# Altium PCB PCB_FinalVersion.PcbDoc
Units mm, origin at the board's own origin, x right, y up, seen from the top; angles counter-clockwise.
Board outline 269.9 x 119.9 mm, 2 copper layers (Top Layer, Bottom Layer); 54 components, 78 nets, 205 pads, 10 vias.
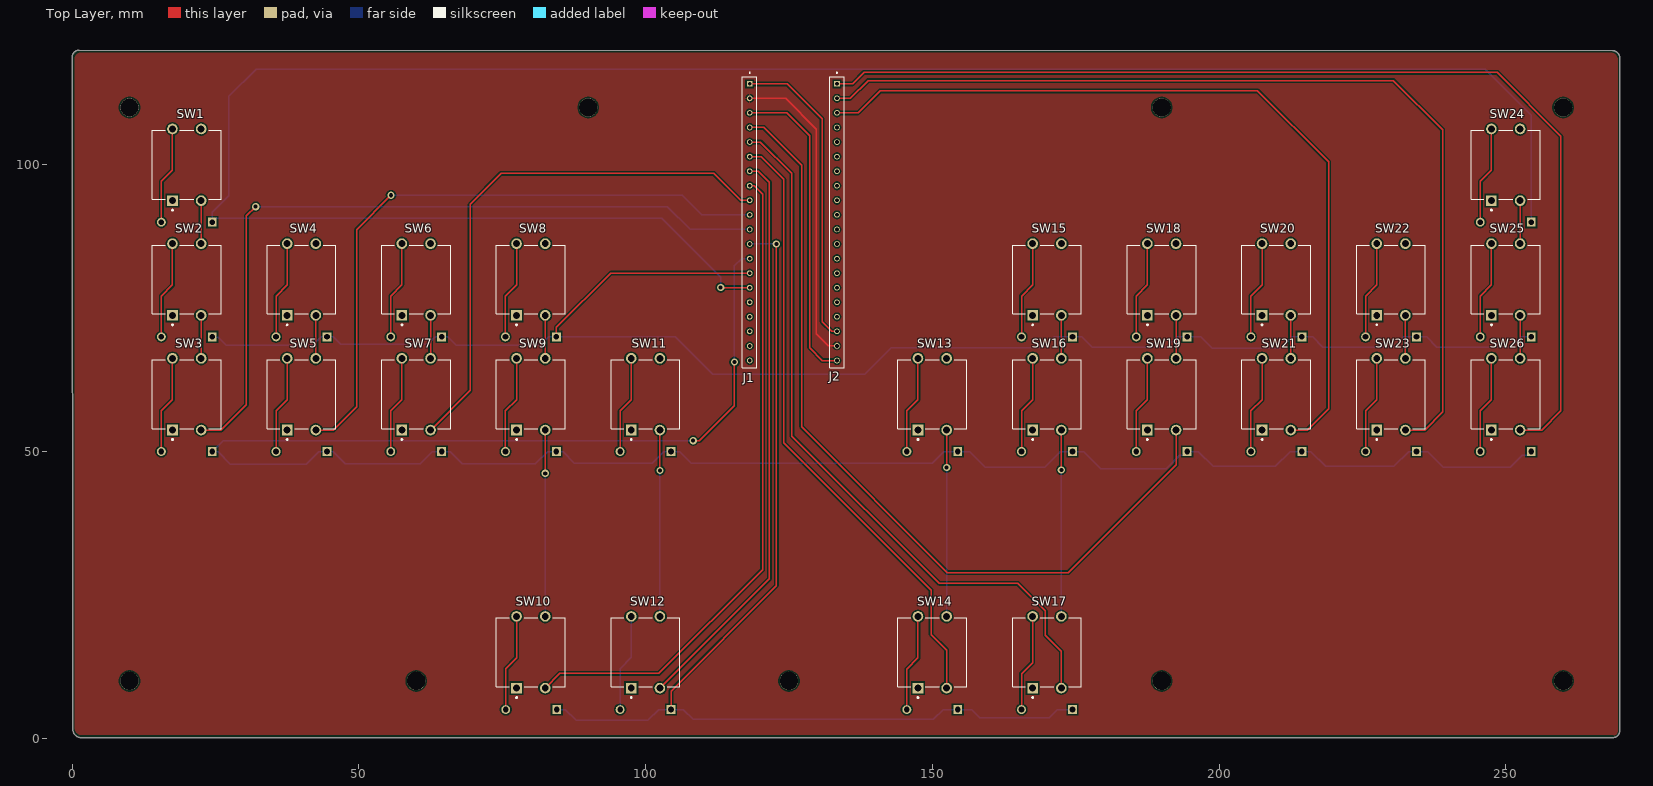
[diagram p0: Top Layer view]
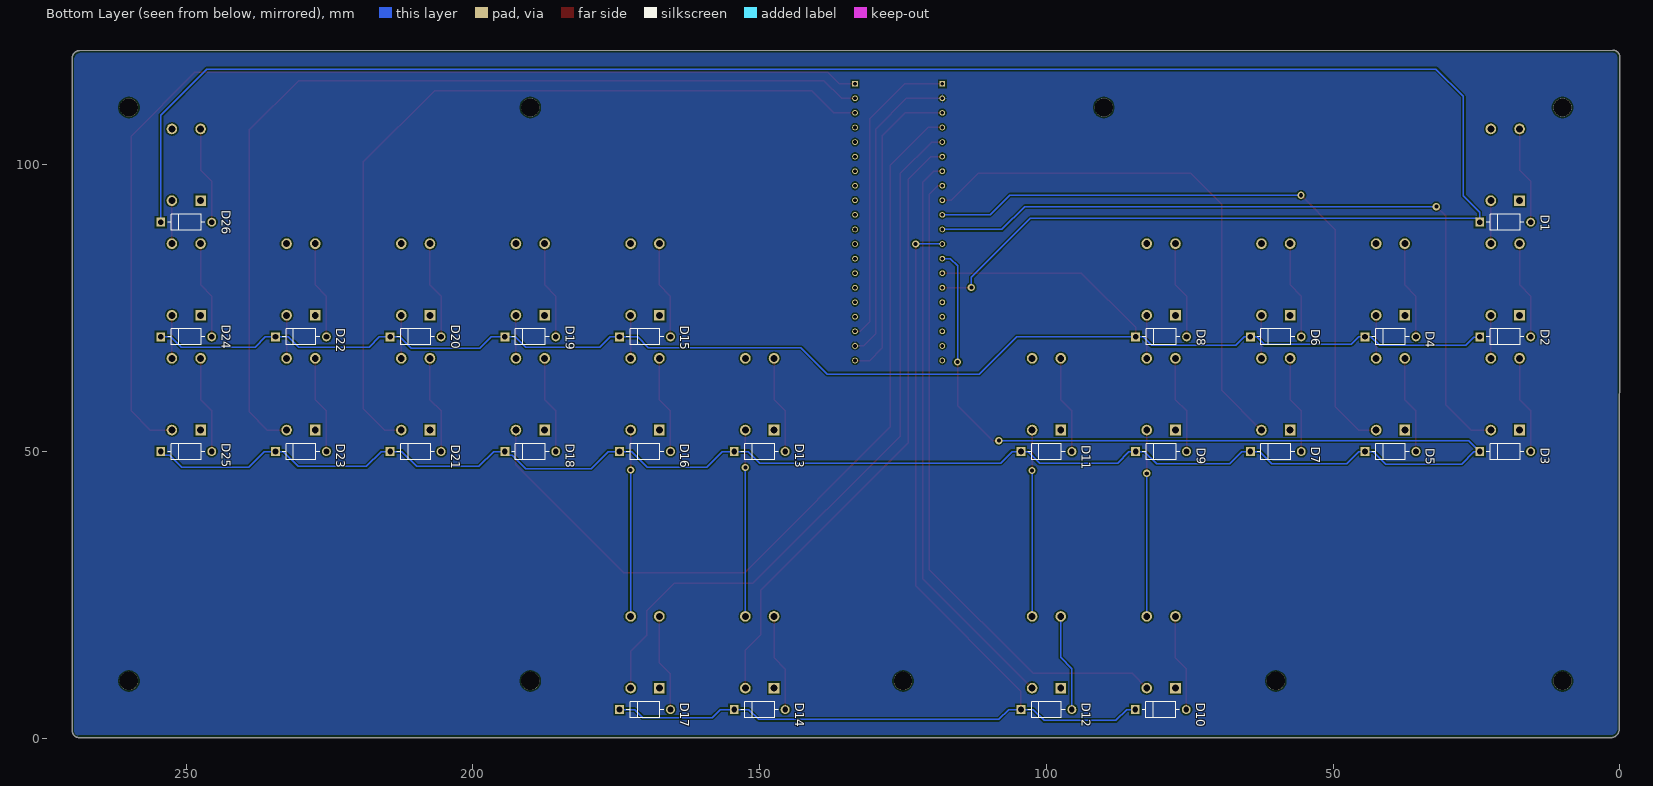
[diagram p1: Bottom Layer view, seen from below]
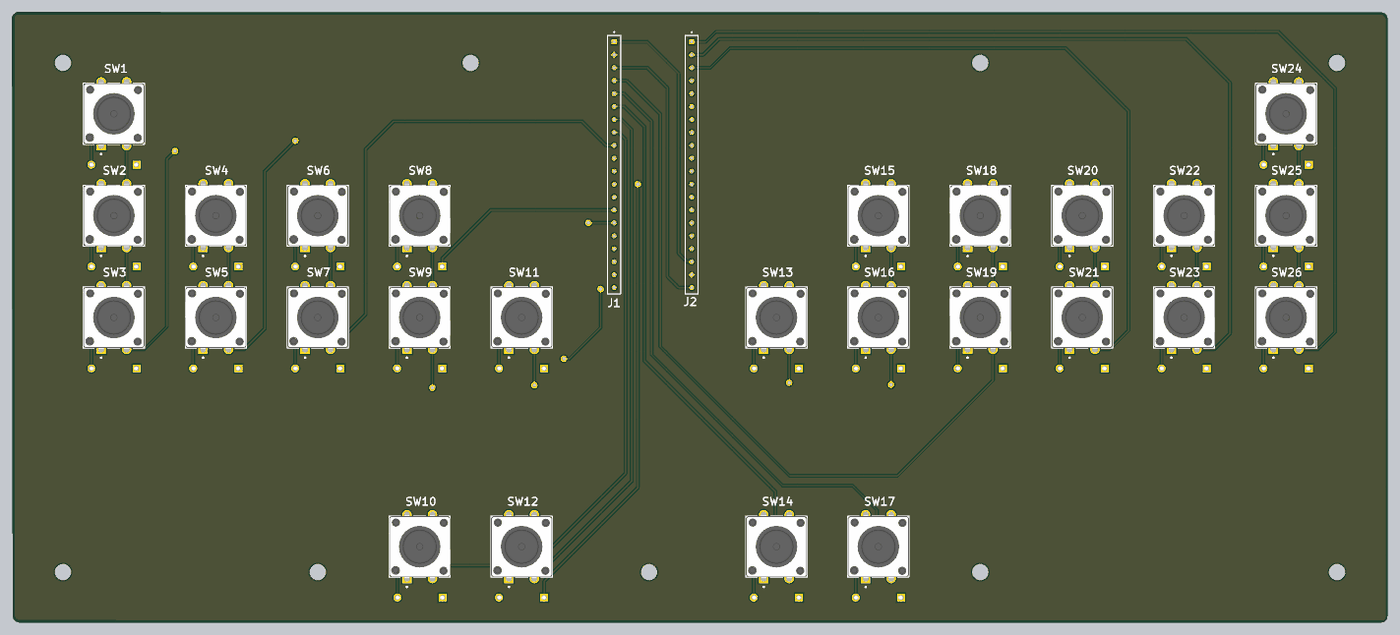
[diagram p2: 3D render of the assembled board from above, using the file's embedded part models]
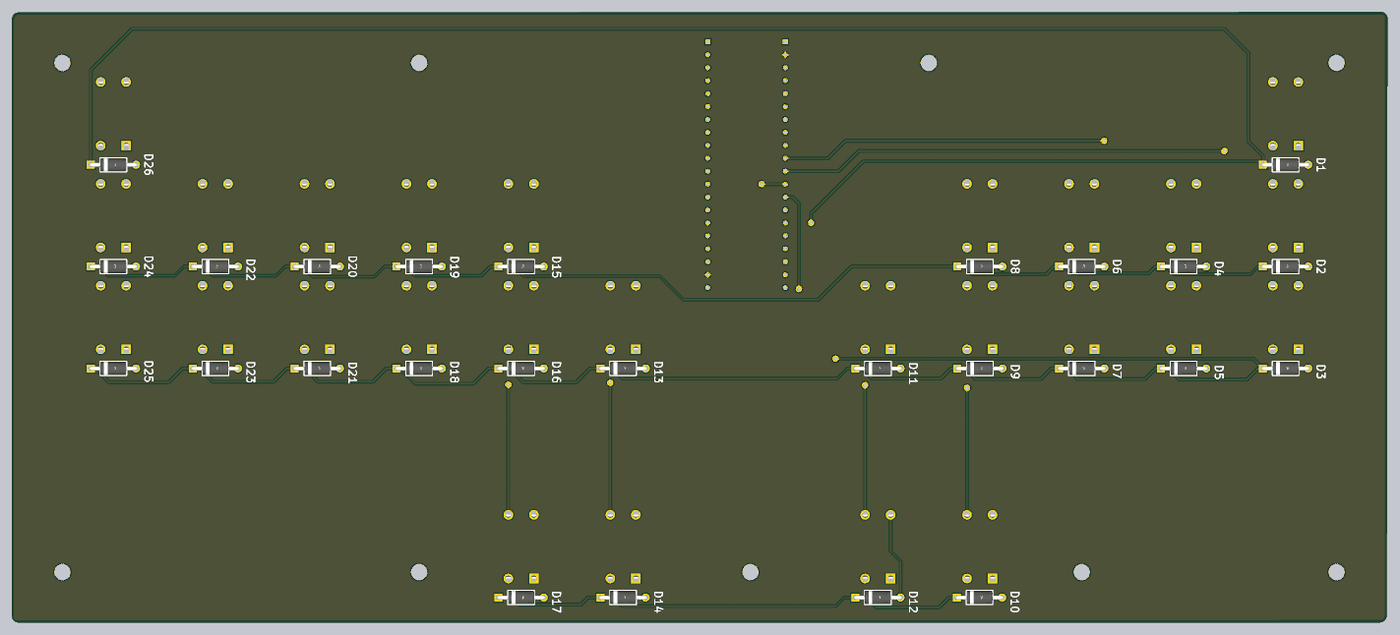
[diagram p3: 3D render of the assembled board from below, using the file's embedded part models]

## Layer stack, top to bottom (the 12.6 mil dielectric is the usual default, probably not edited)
Top Solder: solder mask 0.0102, Solder Resist, Dk 3.5
Top Layer: signal copper 0.0356
Dielectric 1: dielectric 0.32, FR-4, Dk 4.8
Bottom Layer: signal copper 0.0356
Bottom Solder: solder mask 0.0102, Solder Resist, Dk 3.5

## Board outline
0.129,1.541 ccw(c1.57,1.541) 1.57,0.1 5,0.1 268.63,0.1 ccw(c268.63,1.37) 269.9,1.37 269.9,118.63 ccw(c268.63,118.63) 268.63,119.9 1.217,120 ccw(c1.217,118.783) 0,118.783

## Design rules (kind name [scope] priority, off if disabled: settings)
Clearance [All] p1: gap=0.254 ignorepadtopadclearanceinfootprint=FALSE except(0: Arc-Hole Track-Hole SMDPad-Hole THPad-Hole Via-Hole Fill-Hole Poly-Hole Region-Hole Text-Hole)
PolygonConnect [All] p1: connectstyle=Relief reliefconductorwidth=0.254 reliefentries=4 polygonreliefangle="90 Angle" airgapwidth=0.254
RoutingVias [All] p1: holewidth=0.711 width=1.27 viastyle="Through Hole" minholewidth=0.711 minwidth=1.27 maxholewidth=0.711 maxwidth=1.27
SolderMaskExpansion [All] p1: expansion=0.102 istentingtop=FALSE
Width [All] p1: maxlimit=0.5 minlimit=0.254 preferedwidth=0.3
30 further rules are at their usual default settings.

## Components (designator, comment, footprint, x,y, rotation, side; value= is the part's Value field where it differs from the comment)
D1 "1N4007" FP-1N4007-MFG 20,90 r180 bottom value=15pF
D2 "1N4007" FP-1N4007-MFG 20,70 r180 bottom value=15pF
D3 "1N4007" FP-1N4007-MFG 20,50 r180 bottom value=15pF
D4 "1N4007" FP-1N4007-MFG 40,70 r180 bottom value=15pF
D5 "1N4007" FP-1N4007-MFG 40,50 r180 bottom value=15pF
D6 "1N4007" FP-1N4007-MFG 60,70 r180 bottom value=15pF
D7 "1N4007" FP-1N4007-MFG 60,50 r180 bottom value=15pF
D8 "1N4007" FP-1N4007-MFG 80,70 r180 bottom value=15pF
D9 "1N4007" FP-1N4007-MFG 80,50 r180 bottom value=15pF
D10 "1N4007" FP-1N4007-MFG 80.061,5 r180 bottom value=15pF
D11 "1N4007" FP-1N4007-MFG 100,50 r180 bottom value=15pF
D12 "1N4007" FP-1N4007-MFG 100,5 r180 bottom value=15pF
D13 "1N4007" FP-1N4007-MFG 150,50 r180 bottom value=15pF
D14 "1N4007" FP-1N4007-MFG 150,5 r180 bottom value=15pF
D15 "1N4007" FP-1N4007-MFG 170,70 r180 bottom value=15pF
D16 "1N4007" FP-1N4007-MFG 170,50 r180 bottom value=15pF
D17 "1N4007" FP-1N4007-MFG 170,5 r180 bottom value=15pF
D18 "1N4007" FP-1N4007-MFG 190,50 r180 bottom value=15pF
D19 "1N4007" FP-1N4007-MFG 190,70 r180 bottom value=15pF
D20 "1N4007" FP-1N4007-MFG 210,70 r180 bottom value=15pF
D21 "1N4007" FP-1N4007-MFG 210,50 r180 bottom value=15pF
D22 "1N4007" FP-1N4007-MFG 230,70 r180 bottom value=15pF
D23 "1N4007" FP-1N4007-MFG 230,50 r180 bottom value=15pF
D24 "1N4007" FP-1N4007-MFG 250,70 r180 bottom value=15pF
D25 "1N4007" FP-1N4007-MFG 250,50 r180 bottom value=15pF
D26 "1N4007" FP-1N4007-MFG 250,90 r180 bottom value=15pF
J1 "TS-120-T-AA" SAMTEC_TS-120-T-AA 118.156,90 r270 top
J2 "TS-120-T-AA" SAMTEC_TS-120-T-AA 133.376,90 r270 top
SW1 "MJTP1212A" FP-MJTP1212A-MFG 20,100 r90 top
SW2 "MJTP1212A" FP-MJTP1212A-MFG 20,80 r90 top
SW3 "MJTP1212A" FP-MJTP1212A-MFG 20,60 r90 top
SW4 "MJTP1212A" FP-MJTP1212A-MFG 40,80 r90 top
SW5 "MJTP1212A" FP-MJTP1212A-MFG 40,60 r90 top
SW6 "MJTP1212A" FP-MJTP1212A-MFG 60,80 r90 top
SW7 "MJTP1212A" FP-MJTP1212A-MFG 60,60 r90 top
SW8 "MJTP1212A" FP-MJTP1212A-MFG 80,80 r90 top
SW9 "MJTP1212A" FP-MJTP1212A-MFG 80,60 r90 top
SW10 "MJTP1212A" FP-MJTP1212A-MFG 80,15 r90 top
SW11 "MJTP1212A" FP-MJTP1212A-MFG 100,60 r90 top
SW12 "MJTP1212A" FP-MJTP1212A-MFG 100,15 r90 top
SW13 "MJTP1212A" FP-MJTP1212A-MFG 150,60 r90 top
SW14 "MJTP1212A" FP-MJTP1212A-MFG 150,15 r90 top
SW15 "MJTP1212A" FP-MJTP1212A-MFG 170,80 r90 top
SW16 "MJTP1212A" FP-MJTP1212A-MFG 170,60 r90 top
SW17 "MJTP1212A" FP-MJTP1212A-MFG 170,15 r90 top
SW18 "MJTP1212A" FP-MJTP1212A-MFG 190,80 r90 top
SW19 "MJTP1212A" FP-MJTP1212A-MFG 190,60 r90 top
SW20 "MJTP1212A" FP-MJTP1212A-MFG 210,80 r90 top
SW21 "MJTP1212A" FP-MJTP1212A-MFG 210,60 r90 top
SW22 "MJTP1212A" FP-MJTP1212A-MFG 230,80 r90 top
SW23 "MJTP1212A" FP-MJTP1212A-MFG 230,60 r90 top
SW24 "MJTP1212A" FP-MJTP1212A-MFG 250,100 r90 top
SW25 "MJTP1212A" FP-MJTP1212A-MFG 250,80 r90 top
SW26 "MJTP1212A" FP-MJTP1212A-MFG 250,60 r90 top

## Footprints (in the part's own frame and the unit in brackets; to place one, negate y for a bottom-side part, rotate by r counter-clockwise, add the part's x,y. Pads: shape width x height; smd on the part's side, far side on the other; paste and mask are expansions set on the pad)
FP-1N4007-MFG [mm]
  rect 1.55x1.55 hole 1 paste-2539.97 mask+0: 1(-4.44,0)
  round 1.55 hole 1 paste-2539.97 mask+0: 2(4.44,0)
  silkscreen extent -3.27,-1.4 3.27,1.4, body extent -4.83,-1.29 4.83,1.29, height 2.6
FP-MJTP1212A-MFG [mm]
  rect 1.85x1.85 hole 1.2 paste-2539.97 mask+0: 1(-6.25,2.5)
  round 1.85 hole 1.2 paste-2539.97 mask+0: 2(6.25,2.5) 3(-6.25,-2.5) 4(6.25,-2.5)
  silkscreen extent -8.02,-6 6,6, body extent -7.27,-6.1 7.27,6.1, height 0.25
SAMTEC_TS-120-T-AA [mm]
  rect 0.985x0.985 / inner round 0.985 / far side rect 0.985x0.985 hole 0.635: 01(-24.13,0)
  round 0.985 hole 0.635: 02(-21.59,0) 03(-19.05,0) 04(-16.51,0) 05(-13.97,0) 06(-11.43,0) 07(-8.89,0) 08(-6.35,0) 09(-3.81,0) 10(-1.27,0) 11(1.27,0) 12(3.81,0) 13(6.35,0) 14(8.89,0) 15(11.43,0) 16(13.97,0) 17(16.51,0) 18(19.05,0) 19(21.59,0) 20(24.13,0)
  silkscreen extent -26.15,-1.27 25.4,1.27

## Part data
D1 D2 D3 D4 D5 D6 D7 D8 D9 D10 D11 D12 D13 D14 D15 D16 D17 D18 D19 D20 D21 D22 D23 D24 D25 D26: library part CMP-123542-000001-1, "Rectifier diode 1000 V 1 A DO-41, ,", Capacitance=15pF, Forward Current=1A, Manufacturer=Diotec, Max Junction Temp=+175°C, Max Repetitive Reverse Voltage=1000V, Max Surge Forward Current=27A, Peak Reverse Current=5uA, Temperature="-50°C to +175°C", Temperature Range Low=-50°C
J1 J2: "Headers & Wire Housings .100 Single Row Screw Machine Terminal Strip", Package=None
SW1 SW2 SW3 SW4 SW5 SW6 SW7 SW8 SW9 SW10 SW11 SW12 SW13 SW14 SW15 SW16 SW17 SW18 SW19 SW20 SW21 SW22 SW23 SW24 SW25 SW26: library part CMP-47024-000003-1, "SWITCH TACTILE SPST-NO 0.05A 12V", Contact Resistance=100mR, Current Rating=50mA, Max Operating Temperature=70°C, Max Voltage Rating (DC)=12V, Min Operating Temperature=-20°C, Operating Force=160gf, Package Quantity=100

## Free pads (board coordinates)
  round 3.2 hole 3.2: 4(10,10) 4(10,110) 4(60,10) 4(90,110) 4(125,10) 4(190,10) 4(190,110) 4(260,10) 4(260,110)

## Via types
v1: diameter 1.27, hole 0.711, Top Layer to Bottom Layer, 10 vias

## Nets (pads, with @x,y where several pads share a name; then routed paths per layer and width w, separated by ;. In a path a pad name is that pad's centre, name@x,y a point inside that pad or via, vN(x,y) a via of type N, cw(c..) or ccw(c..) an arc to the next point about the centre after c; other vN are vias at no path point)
3.3V: J1.03 J2.20 | length 54.8
  Top Layer w0.254: J1.03 124.65,109.05 128.6,105.1 128.6,68.1 130.83,65.87 J2.20
5V: J1.01 J2.18 | length 53.8
  Top Layer w0.254: J1.01 124.67,114.13 130.8,108 130.8,72.6 132.45,70.95 J2.18
A8: J2.05
A9: J2.06
A10: J2.07
A11: J2.08
A12: J2.09
A15: J2.10
B3: J2.11
B4: J2.12
B5: J2.13
B6: J2.14
B7: J2.15
B8: J2.16
B9: J2.17
B15: J2.04
C13: J1.19
C14: J1.18
C15: J1.17
Column1: J1.11 SW3.3 | length 132.7
  Top Layer w0.254: SW3.3 25.95,53.75 30.4,58.2 30.4,91.1 v1(32,92.7)
  Bottom Layer w0.254: v1(32,92.7) 103.8,92.7 107.77,88.73 J1.11
Column2: J1.10 SW5.3 | length 112.1
  Top Layer w0.254: SW5.3 45.55,53.75 49.6,57.8 49.6,88.7 v1(55.6,94.7)
  Bottom Layer w0.254: v1(55.6,94.7) 106.4,94.7 109.83,91.27 J1.10
Column3: J1.09 SW7.3 | length 95.1
  Top Layer w0.254: SW7.3 69.4,60.65 69.4,93.1 74.8,98.5 111.9,98.5 116.59,93.81 J1.09
Column4: J1.08 SW10.3 | length 114.8
  Top Layer w0.254: SW10.3 85.05,11.3 102.3,11.3 120.4,29.4 120.4,94.9 118.95,96.35 J1.08
Column5: J1.07 SW12.3 | length 100.3
  Top Layer w0.254: SW12.3 121.6,27.85 121.6,96.93 119.64,98.89 J1.07
Column6: J1.06 SW14.3 | length 108.1
  Top Layer w0.254: J1.06 120.17,101.43 124.1,97.5 124.1,51.5 149.8,25.8 149.8,18.091 152.5,15.391 SW14.3
Column7: J1.05 SW17.3 | length 126.9
  Top Layer w0.254: J1.05 120.03,103.97 125.5,98.5 125.5,52.7 151.2,27 164.9,27 169.7,22.2 169.7,18 172.5,15.2 SW17.3
Column8: J1.04 SW19.3 | length 147
  Top Layer w0.254: J1.04 120.59,106.51 127.2,99.9 127.2,54.3 152.6,28.9 173.7,28.9 192.5,47.7 SW19.3
Column9: J2.03 SW21.3 | length 143.6
  Top Layer w0.254: J2.03 137.05,109.05 140.9,112.9 206.7,112.9 219.1,100.5 219.1,57.5 215.35,53.75 SW21.3
Column10: J2.02 SW23.3 | length 167.5
  Top Layer w0.254: J2.02 135.69,111.59 138.8,114.7 230.4,114.7 239,106.1 239,56.9 235.85,53.75 SW23.3
Column11: J2.01 SW26.3 | length 188
  Top Layer w0.254: J2.01 136.13,114.13 138.1,116.1 248.5,116.1 259.6,105 259.6,57.1 256.25,53.75 SW26.3
GND: J1.02 J2.19 | length 54
  Top Layer w0.254: J1.02 124.41,111.59 129.8,106.2 129.8,70.5 131.89,68.41 J2.19
NetD1_2: D1.2 SW1.2 | length 17.1
  Top Layer w0.254: D1.2 15.56,97.114 17.5,99.054 SW1.2
NetD2_2: D2.2 SW2.2 | length 17.1
  Top Layer w0.254: D2.2 15.56,77.114 17.5,79.054 SW2.2
NetD3_2: D3.2 SW3.2 | length 17.1
  Top Layer w0.254: D3.2 15.56,57.114 17.5,59.054 SW3.2
NetD4_2: D4.2 SW4.2 | length 17.1
  Top Layer w0.254: D4.2 35.56,77.114 37.5,79.054 SW4.2
NetD5_2: D5.2 SW5.2 | length 17.1
  Top Layer w0.254: D5.2 35.56,57.114 37.5,59.054 SW5.2
NetD6_2: D6.2 SW6.2 | length 17.1
  Top Layer w0.254: D6.2 55.56,77.114 57.5,79.054 SW6.2
NetD7_2: D7.2 SW7.2 | length 17.1
  Top Layer w0.254: D7.2 55.56,57.114 57.5,59.054 SW7.2
NetD8_2: D8.2 SW8.2 | length 17.1
  Top Layer w0.254: D8.2 75.56,77.114 77.5,79.054 SW8.2
NetD9_2: D9.2 SW9.2 | length 17.1
  Top Layer w0.254: D9.2 75.56,57.114 77.5,59.054 SW9.2
NetD10_2: D10.2 SW10.2 | length 17
  Top Layer w0.254: D10.2 75.621,12.145 77.5,14.024 SW10.2
NetD11_2: D11.2 SW11.2 | length 17.1
  Top Layer w0.254: D11.2 95.56,57.114 97.5,59.054 SW11.2
NetD12_2: D12.2 SW12.2 | length 17.1
  Bottom Layer w0.254: D12.2 95.56,12.16 97.5,14.1 SW12.2
NetD13_2: D13.2 SW13.2 | length 17.1
  Top Layer w0.254: D13.2 145.56,57.114 147.5,59.054 SW13.2
NetD14_2: D14.2 SW14.2 | length 17.1
  Top Layer w0.254: D14.2 145.56,12.06 147.5,14 SW14.2
NetD15_2: D15.2 SW15.2 | length 17.1
  Top Layer w0.254: D15.2 165.56,77.114 167.5,79.054 SW15.2
NetD16_2: D16.2 SW16.2 | length 17.1
  Top Layer w0.254: D16.2 165.56,57.114 167.5,59.054 SW16.2
NetD17_2: D17.2 SW17.2 | length 17.1
  Top Layer w0.254: D17.2 165.56,11.26 167.5,13.2 SW17.2
NetD18_2: D18.2 SW19.2 | length 17.1
  Top Layer w0.254: D18.2 185.56,57.114 187.5,59.054 SW19.2
NetD19_2: D19.2 SW18.2 | length 17.1
  Top Layer w0.254: D19.2 185.56,77.114 187.5,79.054 SW18.2
NetD20_2: D20.2 SW20.2 | length 17.1
  Top Layer w0.254: D20.2 205.56,77.114 207.5,79.054 SW20.2
NetD21_2: D21.2 SW21.2 | length 17.1
  Top Layer w0.254: D21.2 205.56,57.114 207.5,59.054 SW21.2
NetD22_2: D22.2 SW22.2 | length 17.1
  Top Layer w0.254: D22.2 225.56,77.114 227.5,79.054 SW22.2
NetD23_2: D23.2 SW23.2 | length 17.1
  Top Layer w0.254: D23.2 225.56,57.114 227.5,59.054 SW23.2
NetD24_2: D24.2 SW25.2 | length 17.1
  Top Layer w0.254: D24.2 245.56,77.114 247.5,79.054 SW25.2
NetD25_2: D25.2 SW26.2 | length 17.1
  Top Layer w0.254: D25.2 245.56,57.114 247.5,59.054 SW26.2
NetD26_2: D26.2 SW24.2 | length 17.1
  Top Layer w0.254: D26.2 245.56,97.114 247.5,99.054 SW24.2
NetSW1_3: SW1.3 SW2.4 | length 7.5
  Top Layer w0.254: SW2.4 SW1.3
NetSW2_3: SW2.3 SW3.4 | length 7.5
  Top Layer w0.254: SW3.4 SW2.3
NetSW4_3: SW4.3 SW5.4 | length 7.5
  Top Layer w0.254: SW5.4 SW4.3
NetSW6_3: SW6.3 SW7.4 | length 7.5
  Top Layer w0.254: SW7.4 SW6.3
NetSW8_3: SW8.3 SW9.4 | length 7.5
  Top Layer w0.254: SW9.4 SW8.3
NetSW9_3: SW9.3 SW10.4 | length 32.5
  Top Layer w0.254: v1(82.5,46.2) SW9.3
  Bottom Layer w0.254: SW10.4 v1(82.5,46.2)
NetSW11_3: SW11.3 SW12.4 | length 32.5
  Top Layer w0.254: v1(102.5,46.7) SW11.3
  Bottom Layer w0.254: SW12.4 v1(102.5,46.7)
NetSW13_3: SW13.3 SW14.4 | length 32.5
  Top Layer w0.254: v1(152.5,47.2) SW13.3
  Bottom Layer w0.254: SW14.4 v1(152.5,47.2)
NetSW15_3: SW15.3 SW16.4 | length 7.5
  Top Layer w0.254: SW16.4 SW15.3
NetSW16_3: SW16.3 SW17.4 | length 32.5
  Top Layer w0.254: v1(172.5,46.8) SW16.3
  Bottom Layer w0.254: SW17.4 v1(172.5,46.8)
NetSW18_3: SW18.3 SW19.4 | length 7.5
  Top Layer w0.254: SW19.4 SW18.3
NetSW20_3: SW20.3 SW21.4 | length 7.5
  Top Layer w0.254: SW21.4 SW20.3
NetSW22_3: SW22.3 SW23.4 | length 7.5
  Top Layer w0.254: SW23.4 SW22.3
NetSW24_3: SW24.3 SW25.4 | length 7.5
  Top Layer w0.254: SW25.4 SW24.3
NetSW25_3: SW25.3 SW26.4 | length 7.5
  Top Layer w0.254: SW26.4 SW25.3
R: J1.16
Row1: D1.1 D26.1 J1.15 | length 374.3
  Top Layer w0.254: v1(113.1,78.6) 113.115,78.585 118.141,78.585 J1.15
  Bottom Layer w0.254: v1(113.1,78.6) 113.1,80.4 102.8,90.7 25.237,90.7 25.185,90.648 25.088,90.648 D1.1 24.44,91.74 27.3,94.6 27.3,111.928 32.072,116.7 246.4,116.7 254.44,108.66 D26.1
Row2: D2.1 D4.1 D6.1 D8.1 D15.1 D19.1 D20.1 D22.1 D24.1 J1.14 | length 284.4
  Top Layer w0.254: D8.1 84.44,71.64 93.91,81.11 J1.14
  Bottom Layer w0.254: D2.1 24.487,69.953 25.447,69.953 26.9,68.5 41.9,68.5 43.4,70 45.5,70 46.8,68.7 62,68.7 63.3,70 65.5,70 67,68.5 81.6,68.5 83.1,70 D8.1 105.2,70 111.7,63.5 138.2,63.5 142.8,68.1 169.4,68.1 171.3,70 D15.1 176.1,70 177.9,68.2 190.8,68.2 192.6,70 D19.1 196.8,70 198.8,68 210.8,68 212.8,70 D20.1 216.3,70 218.1,68.2 230.4,68.2 232.2,70 D22.1 236.2,70 238,68.2 250.9,68.2 252.7,70 D24.1
Row3: D3.1 D5.1 D7.1 D9.1 D11.1 D13.1 D16.1 D18.1 D21.1 D23.1 D25.1 J1.13 | length 371.8
  Top Layer w0.254: v1(108.3,51.9) 109.4,51.9 115.5,58 v1(115.5,65.6)
  Bottom Layer w0.254: v1(108.3,51.9) 26.34,51.9 D3.1 24.487,49.953 25.447,49.953 27.6,47.8 40.8,47.8 43,50 D5.1 45.5,50 47.6,47.9 60.7,47.9 62.8,50 D7.1 65.9,50 68,47.9 80.8,47.9 82.9,50 D9.1 85.6,50 87.6,48 101.2,48 103.2,50 D11.1 106,50 108,48 150,48 152,50 D13.1 156.5,50 159.2,47.3 169.6,47.3 172.3,50 D16.1 176.4,50 179.4,47 190.8,47 193.152,49.352 193.792,49.352 D18.1 196.4,50 199,47.4 209.8,47.4 212.4,50 D21.1 216,50 218.6,47.4 230.5,47.4 233.1,50 D23.1 236.4,50 239.1,47.3 250.8,47.3 252.852,49.352 253.792,49.352 D25.1 ; v1(115.5,65.6) 115.5,82.4 116.75,83.65 J1.13
Row4: D10.1 D12.1 D14.1 D17.1 J1.12 | length 187.5
  Top Layer w0.254: D12.1 104.44,8.24 122.8,26.6 v1(122.8,86.2)
  Bottom Layer w0.254: D10.1 86,5 87.9,3.1 100.4,3.1 102.3,5 D12.1 106.6,5 108.3,3.3 150.2,3.3 151.9,5 D14.1 156.9,5 158.3,3.6 170.4,3.6 171.8,5 D17.1 ; J1.12 118.161,86.195 122.795,86.195 v1(122.8,86.2)
VB: J1.20
pads on no net: SW1.1 SW1.4 SW2.1 SW3.1 SW4.1 SW4.4 SW5.1 SW6.1 SW6.4 SW7.1 SW8.1 SW8.4 SW9.1 SW10.1 SW11.1 SW11.4 SW12.1 SW13.1 SW13.4 SW14.1 SW15.1 SW15.4 SW16.1 SW17.1 SW18.1 SW18.4 SW19.1 SW20.1 SW20.4 SW21.1 SW22.1 SW22.4 SW23.1 SW24.1 SW24.4 SW25.1 SW26.1

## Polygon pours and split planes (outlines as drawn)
GND on Bottom Layer "GND_L02_P000" (solid, pour order 0): 4.5,0.6 1.5,0.6 cw(c1.5,1.6) 0.5,1.6 0.5,118.8 cw(c1.2,118.8) 1.2,119.5 268.4,119.5 cw(c268.4,118.4) 269.5,118.4 269.5,1.2 cw(c268.8,1.2) 268.8,0.5
GND on Top Layer "GND_L01_P001" (solid, pour order 1): 3.6,0.6 1.6,0.6 cw(c1.6,1.7) 0.5,1.7 0.5,118.7 cw(c1.3,118.7) 1.3,119.5 268.5,119.5 cw(c268.5,118.5) 269.5,118.5 269.5,1.2 cw(c268.8,1.2) 268.8,0.5

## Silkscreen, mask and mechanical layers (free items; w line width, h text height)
Mechanical 1:
  lines w0.254: 5,0.1 5.2,0.1 268.63,0.1 ccw(c268.63,1.37) 269.9,1.37 269.9,1.7 269.9,118.63 ccw(c268.63,118.63) 268.63,119.9 1.217,120 ccw(c1.217,118.783) 0,118.783 0.129,1.541 ccw(c1.57,1.541) 1.57,0.1 5,0.1 ; 5,0.1 5,0.1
